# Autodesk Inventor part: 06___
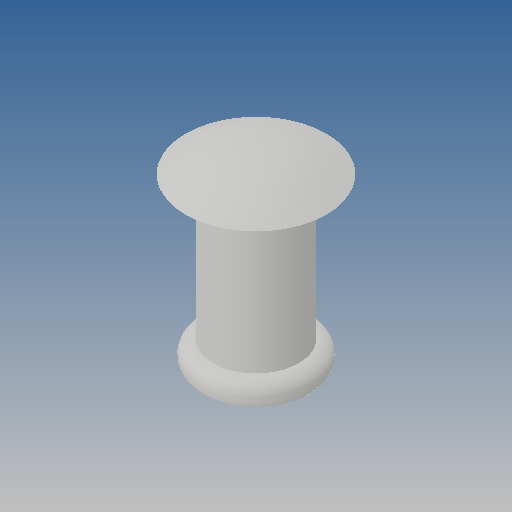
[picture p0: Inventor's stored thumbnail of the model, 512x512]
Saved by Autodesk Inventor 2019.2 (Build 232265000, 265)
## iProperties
Created: 2010-06
Part Number: 06___
Material: Ogólny
Document SubType Name: Modeling
Designer: CADENGINEERING4
Density: 1 g/cm^3
Appearance: Domyślna
Author: CADENGINEERING4
Revision Number: ANY
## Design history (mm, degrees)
feature "NONE"
node "Bryła1"
